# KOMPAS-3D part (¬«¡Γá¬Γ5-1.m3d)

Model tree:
1. Эскиз:1
2. Операция выдавливания:1
     Расстояние 1 = 8; Расстояние 2 = 8
3. Эскиз:2
4. Операция выдавливания:2
     Расстояние 1 = 0.5; Расстояние 2 = 8
5. Скругление:1
     Радиус = 0.3
6. Эскиз:3
7. Операция выдавливания:3
     Расстояние 1 = 0.5; Расстояние 2 = 8
8. Скругление:2
     Радиус = 0.3
9. Эскиз:4
10. Операция выдавливания:4
     Расстояние 1 = 0.5; Расстояние 2 = 6
11. Эскиз:5
12. Вырезать элемент выдавливания:1
     Расстояние 2 = 40; Расстояние 1 = 20
13. Скругление:3
     Радиус = 1.5
14. Эскиз:6
15. Операция выдавливания:5
     Расстояние 1 = 3; Расстояние 2 = 6
16. Эскиз:7
17. Операция выдавливания:6
     Расстояние 1 = 0.1; Расстояние 2 = 2
18. Эскиз:8
19. Операция выдавливания:7
     Расстояние 1 = 0.7; Расстояние 2 = 2
20. Скругление:5
     Радиус = 0.2
21. Скругление:6
     Радиус = 1
22. Эскиз:9
23. Операция выдавливания:8
     Расстояние 1 = 3; Расстояние 2 = 4
24. Скругление:7
     Радиус = 0.3
25. Эскиз:10
26. Операция выдавливания:9
     Расстояние 1 = 8.7; Расстояние 2 = 38
27. Эскиз:11
28. Вырезать элемент выдавливания:2
     Расстояние 1 = 15.3999
29. Эскиз:12
30. Вырезать элемент выдавливания:3
     Расстояние 1 = 0.3
31. Эскиз:13
32. Вырезать элемент выдавливания:4
     Расстояние 1 = 0.3
33. Эскиз:14
34. Вырезать элемент выдавливания:5
     Расстояние 1 = 15.0999
35. Скругление:8
     Радиус = 0.1
36. Скругление:9
     Радиус = 0.2
37. Эскиз:15
38. Операция выдавливания:10
     Расстояние 1 = 1; Расстояние 2 = 38
39. Эскиз:16
40. Операция выдавливания:11
     Расстояние 1 = 1
41. Эскиз:17
42. Операция выдавливания:12
     Расстояние 1 = 0.1; Расстояние 2 = 1
43. Эскиз:18
44. Операция выдавливания:13
     Расстояние 1 = 0.1; Расстояние 2 = 3
45. Эскиз:19
46. Операция выдавливания:14
     Расстояние 1 = 0.5; Расстояние 2 = 3
47. Эскиз:20
48. Операция выдавливания:15
     Расстояние 1 = 0.5; Расстояние 2 = 3

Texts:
  контакт5-1
  stalker61
  Сплав АЛ8  ГОСТ 1583-93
